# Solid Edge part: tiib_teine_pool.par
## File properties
Author: Romil
Template: Iso Part.par
Last saved by: Romil
Revision: 4
Application: Solid Edge
Username: Romil
Accuracy: 0.990
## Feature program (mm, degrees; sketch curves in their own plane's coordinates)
body "unnamed Body 1"
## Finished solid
Body 1: solid body, 146 faces, 410 edges, 260 vertices.
  Faces by surface: cylinder 85, plane 56, spline 5
  Edges by curve: line 189, circle 154, ellipse 48, intersection 16, spline 3
Bounding box of the edges (mm; curved faces can reach further): 63.969 x 47.203 x 18.506, from (-63.9691, -23.6008, -3.6077) to (0, 23.6022, 14.8983).
Cylindrical faces by radius (mm): R0.15 x4, R0.2 x1, R0.3 x26, R2.4 x4, R3.1 x8, R3.6 x13, R4.5 x8, R4.5001 x1, R8.4 x1, R23.65 x2, R26.3541 x2, R27.1744 x8, R29.7361 x2, R36.5646 x2, R41.3592 x3
Planar faces by outward normal: +x 15, +y 2, +z 2, -x 7, -y 2, -z 3, oblique 25
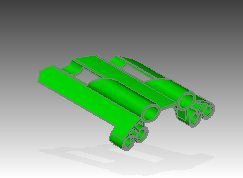
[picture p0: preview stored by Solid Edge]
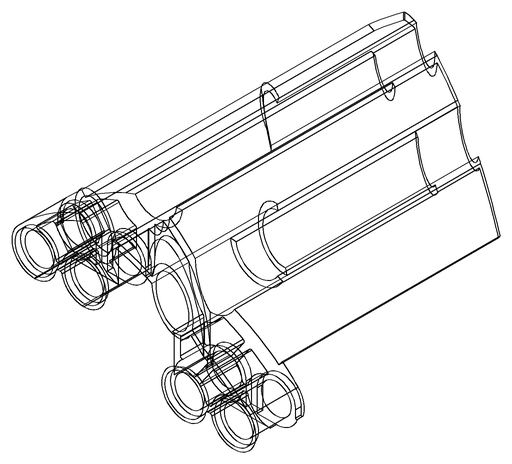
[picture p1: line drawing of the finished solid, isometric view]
